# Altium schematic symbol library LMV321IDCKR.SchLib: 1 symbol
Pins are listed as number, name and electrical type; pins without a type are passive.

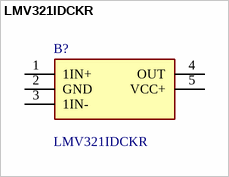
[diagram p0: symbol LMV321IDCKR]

## LMV321IDCKR
designator B?
Single Low-Voltage Rail-to-Rail Output Operational Amplifier  see LMV321A for upgraded version; Manufacturer_Name: Texas Instruments; Geometry.Height: 1.1mm
footprint SOT65P210X110-5N
pins: 1 1IN+, 2 GND, 3 1IN-, 4 OUT, 5 VCC+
